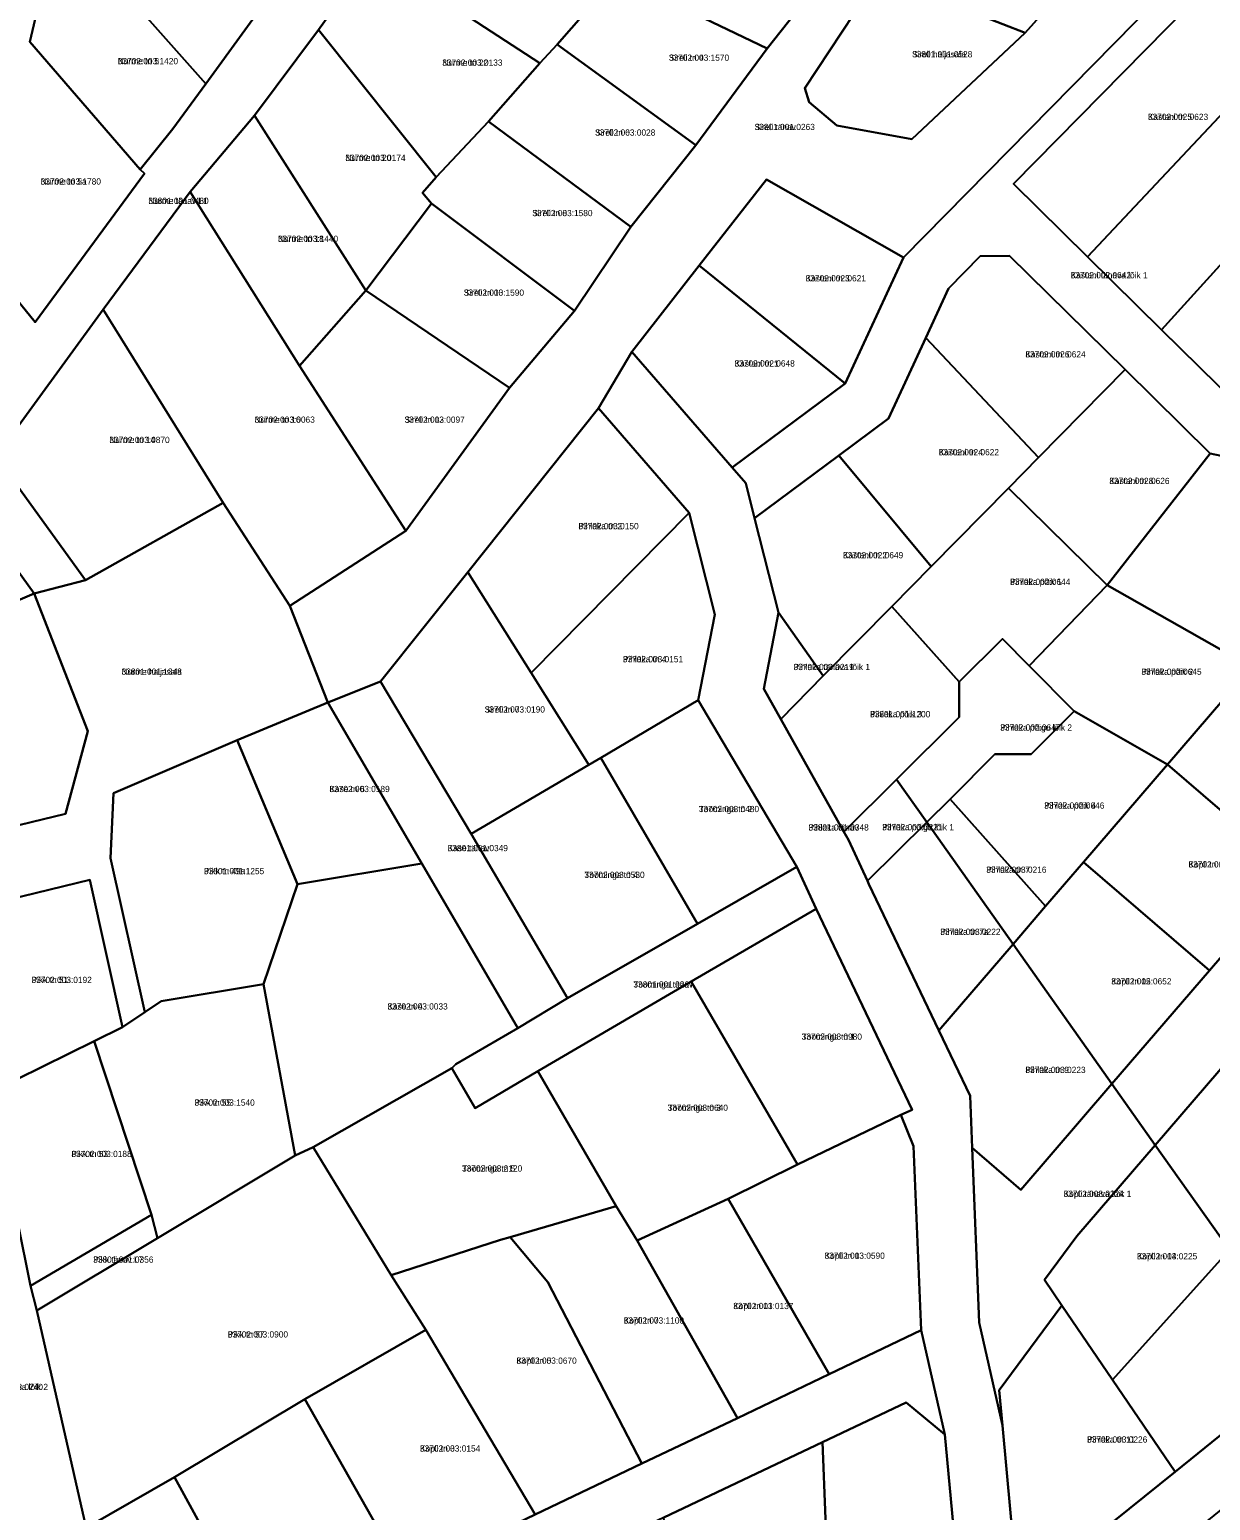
# Model space of a CAD drawing. Extents: x 551583 to 585220, y 6539942 to 6568852.
# Drawn here: x 566836.4 to 567120.7, y 6560564.2 to 6560920.6 of the extents above; entities that cross this region are included whole.
import ezdxf

# ---------------------------------------------------------------- set-up
doc = ezdxf.new("R2010")
doc.units = 0
for name, color, linetype in [('L_AADRESS', 7, 'Continuous'), ('PIIR', 7, 'Continuous'), ('TUNNUS', 7, 'Continuous')]:
    doc.layers.add(name, color=color, linetype=linetype)

msp = doc.modelspace()

# ---------------------------------------------------------------- linework, layer by layer
at = {"layer": 'PIIR'}
for points in [[(567103.65, 6560958.96), (567105.34, 6560952.59), (567076.12, 6560919.88), (567054.59, 6560928.31), (567066.71, 6560957.02), (567070.6, 6560967.27), (567072.05, 6560971.64)], [(566824.24, 6560964.21), (566848.08, 6560967.35), (566843.44, 6560947.46), (566836.5, 6560917.68), (566863.07, 6560886.94), (566864.07, 6560886.01), (566837.76, 6560850.18), (566827.3, 6560862.99), (566826.14, 6560904.44), (566821.12, 6560930.5), (566814.13, 6560962.93)], [(566906.38, 6560945.57), (566878.83, 6560907.59), (566843.44, 6560947.46), (566848.08, 6560967.35), (566866.74, 6560969.67), (566894.71, 6560952.95)], [(566931.8, 6560955.94), (566977.76, 6560933.49), (566963.43, 6560917.09), (566959.26, 6560912.6), (566919.09, 6560938.77)], [(566977.76, 6560933.49), (566988.09, 6560955.16), (567007.18, 6560946.96), (567030.82, 6560937.46), (567013.96, 6560916.09)], [(566878.83, 6560907.59), (566870.93, 6560896.74), (566863.07, 6560886.94), (566836.5, 6560917.68), (566843.44, 6560947.46)], [(566919.09, 6560938.77), (566959.26, 6560912.6), (566946.87, 6560898.56), (566934.32, 6560885.13), (566905.97, 6560920.56)], [(567073.26, 6560883.48), (567126.11, 6560937.17), (567138.02, 6560915.86), (567091.08, 6560865.94)], [(566963.43, 6560917.09), (566977.76, 6560933.49), (567013.96, 6560916.09), (566996.82, 6560892.79)], [(567023.08, 6560906.52), (567040.84, 6560933.6), (567054.59, 6560928.31), (567076.12, 6560919.88), (567048.78, 6560894.31), (567030.72, 6560897.59), (567024.08, 6560903.14)], [(566890.53, 6560899.97), (566905.97, 6560920.56), (566934.32, 6560885.13), (566931.02, 6560881.32), (566933.19, 6560878.76), (566917.34, 6560857.85)], [(566996.82, 6560892.79), (566981.15, 6560873.16), (566946.87, 6560898.56), (566959.26, 6560912.6), (566963.43, 6560917.09)], [(567091.08, 6560865.94), (567138.02, 6560915.86), (567150.25, 6560893.97), (567108.9, 6560848.4)], [(566890.53, 6560899.97), (566917.34, 6560857.85), (566901.42, 6560839.74), (566875.06, 6560881.6)], [(566931.02, 6560881.32), (566934.32, 6560885.13), (566946.87, 6560898.56), (566981.15, 6560873.16), (566967.56, 6560852.91), (566933.19, 6560878.76)], [(567108.9, 6560848.4), (567150.25, 6560893.97), (567151.94, 6560890.96), (567168.99, 6560898.46), (567175.99, 6560888.5), (567127.03, 6560830.55)], [(566875.06, 6560881.6), (566901.42, 6560839.74), (566927.02, 6560799.96), (566899.11, 6560781.95), (566882.99, 6560806.76), (566854.16, 6560853.3)], [(566997.64, 6560863.86), (567013.84, 6560884.59), (567046.8, 6560865.82), (567032.77, 6560835.46)], [(566933.19, 6560878.76), (566967.56, 6560852.91), (566951.94, 6560834.4), (566917.34, 6560857.85)], [(566981.44, 6560843.11), (566997.64, 6560863.86), (567032.77, 6560835.46), (567005.55, 6560815.21)], [(567052.14, 6560846.42), (567057.64, 6560858.34), (567065.27, 6560866.09), (567072.34, 6560866.15), (567100.13, 6560838.79), (567079.33, 6560817.66)], [(566901.42, 6560839.74), (566917.34, 6560857.85), (566951.94, 6560834.4), (566927.02, 6560799.96)], [(566854.16, 6560853.3), (566882.99, 6560806.76), (566849.86, 6560788.08), (566828.29, 6560817.87)], [(567031.24, 6560818.12), (567043.19, 6560827.01), (567052.14, 6560846.42), (567079.33, 6560817.66), (567072.07, 6560810.28), (567053.49, 6560791.4)], [(567072.07, 6560810.28), (567079.33, 6560817.66), (567100.13, 6560838.79), (567120.61, 6560818.64), (567095.83, 6560786.9)], [(566941.89, 6560790.02), (566973.41, 6560829.49), (566995.18, 6560804.31), (566957.13, 6560765.81)], [(567010.96, 6560803.02), (567031.24, 6560818.12), (567053.49, 6560791.4), (567044.03, 6560781.77), (567027.5, 6560765.04), (567016.71, 6560780.33)], [(567095.83, 6560786.9), (567120.61, 6560818.64), (567150.12, 6560812.31), (567123.42, 6560771.28)], [(567096.98, 6560666.86), (567120.45, 6560694.15), (567140.67, 6560717.66), (567160.88, 6560741.16), (567165.44, 6560746.47), (567192.97, 6560778.47), (567201.51, 6560788.4), (567226.17, 6560817.09), (567236.58, 6560802.28), (567212.89, 6560774.8), (567204.12, 6560764.6), (567174, 6560729.58), (567154.06, 6560706.39), (567132.1, 6560680.86), (567107.4, 6560652.13)], [(566783.62, 6560793.33), (566817.83, 6560812.12), (566837.54, 6560784.9), (566793.43, 6560766.04)], [(567044.03, 6560781.77), (567053.49, 6560791.4), (567072.07, 6560810.28), (567095.83, 6560786.9), (567077.03, 6560767.52), (567070.64, 6560773.95), (567060.23, 6560763.63)], [(566849.86, 6560788.08), (566882.99, 6560806.76), (566899.11, 6560781.95), (566908.2, 6560758.66), (566886.39, 6560749.58), (566856.6, 6560736.84), (566855.9, 6560721.21), (566864.13, 6560684.11), (566858.79, 6560680.48), (566850.93, 6560715.95), (566815.01, 6560707.21), (566808.94, 6560723.09), (566845.05, 6560731.87), (566850.45, 6560751.75), (566837.54, 6560784.9)], [(566957.13, 6560765.81), (566995.18, 6560804.31), (567001.35, 6560779.88), (566997.4, 6560759.23), (566973.93, 6560745.35), (566971.06, 6560743.67)], [(566920.91, 6560763.75), (566941.89, 6560790.02), (566957.13, 6560765.81), (566971.06, 6560743.67), (566942.76, 6560727.08)], [(567077.03, 6560767.52), (567095.83, 6560786.9), (567123.42, 6560771.28), (567130.55, 6560767.24), (567110.34, 6560743.74), (567087.91, 6560756.57)], [(566793.43, 6560766.04), (566837.54, 6560784.9), (566850.45, 6560751.75), (566845.05, 6560731.87), (566808.94, 6560723.09)], [(567027.5, 6560765.04), (567044.03, 6560781.77), (567060.23, 6560763.63), (567060.2, 6560755.12), (567045.14, 6560740.1), (567032.46, 6560727.52), (567017.28, 6560754.61)], [(567013.19, 6560761.95), (567016.71, 6560780.33), (567027.5, 6560765.04), (567017.28, 6560754.61)], [(567045.14, 6560740.1), (567060.2, 6560755.12), (567060.23, 6560763.63), (567070.64, 6560773.95), (567077.03, 6560767.52), (567087.91, 6560756.57), (567077.52, 6560746.24), (567068.79, 6560746.26), (567058.07, 6560735.41), (567052.43, 6560729.83)], [(566930.82, 6560719.87), (566908.2, 6560758.66), (566920.91, 6560763.75), (566942.74, 6560727.05), (566965.93, 6560687.48), (566953.93, 6560680.23)], [(567110.34, 6560743.74), (567130.55, 6560767.24), (567144.77, 6560755.02), (567155.57, 6560745.72), (567160.88, 6560741.16), (567140.67, 6560717.66)], [(566886.39, 6560749.58), (566908.2, 6560758.66), (566930.82, 6560719.87), (566900.9, 6560714.94)], [(566997.4, 6560759.23), (567021.13, 6560719.07), (566997.23, 6560705.36), (566973.93, 6560745.35)], [(567058.07, 6560735.41), (567068.79, 6560746.26), (567077.52, 6560746.24), (567087.91, 6560756.57), (567110.34, 6560743.74), (567090.13, 6560720.23), (567081.01, 6560709.63)], [(566855.9, 6560721.21), (566856.6, 6560736.84), (566886.39, 6560749.58), (566900.9, 6560714.94), (566892.74, 6560690.87), (566868.08, 6560686.79), (566864.13, 6560684.11)], [(566973.93, 6560745.35), (566997.23, 6560705.36), (566965.93, 6560687.48), (566942.74, 6560727.05), (566971.06, 6560743.67)], [(567090.13, 6560720.23), (567110.34, 6560743.74), (567140.67, 6560717.66), (567120.45, 6560694.15)], [(567032.46, 6560727.52), (567045.14, 6560740.1), (567052.43, 6560729.83), (567038.13, 6560715.69), (567033.56, 6560725.6)], [(567052.43, 6560729.83), (567058.07, 6560735.41), (567081.01, 6560709.63), (567073.17, 6560700.52)], [(567038.13, 6560715.69), (567052.43, 6560729.83), (567073.17, 6560700.52), (567055.3, 6560679.73), (567038.48, 6560714.92)], [(566930.82, 6560719.87), (566953.93, 6560680.23), (566939.06, 6560671.6), (566938.1, 6560670.66), (566904.65, 6560651.59), (566900.32, 6560649.63), (566892.74, 6560690.87), (566900.9, 6560714.94)], [(566997.23, 6560705.36), (567021.13, 6560719.07), (567025.75, 6560709), (566995.68, 6560691.51), (566958.8, 6560669.89), (566943.71, 6560661), (566938.1, 6560670.66), (566939.06, 6560671.6), (566953.93, 6560680.23), (566965.93, 6560687.48)], [(567073.17, 6560700.52), (567081.01, 6560709.63), (567090.13, 6560720.23), (567120.45, 6560694.15), (567096.98, 6560666.86)], [(566821.78, 6560686.63), (566815.01, 6560707.21), (566850.93, 6560715.95), (566858.79, 6560680.48), (566851.93, 6560677.14), (566827.21, 6560664.95)], [(567025.75, 6560709), (567048.92, 6560660.62), (567046.19, 6560659.36), (567021.26, 6560647.45), (566995.68, 6560691.51)], [(567055.3, 6560679.73), (567073.17, 6560700.52), (567096.98, 6560666.86), (567075.06, 6560641.37), (567063.32, 6560651.47), (567062.82, 6560664)], [(566900.32, 6560649.63), (566867.2, 6560629.72), (566865.77, 6560635.3), (566851.93, 6560677.14), (566858.79, 6560680.48), (566864.13, 6560684.11), (566868.08, 6560686.79), (566892.74, 6560690.87)], [(567021.26, 6560647.45), (567004.57, 6560639.21), (566982.7, 6560629.15), (566977.66, 6560637.4), (566958.8, 6560669.89), (566995.68, 6560691.51)], [(567107.4, 6560652.13), (567132.1, 6560680.86), (567153.34, 6560652.22), (567152.14, 6560651.14), (567125.27, 6560626.87)], [(566827.21, 6560664.95), (566851.93, 6560677.14), (566865.77, 6560635.3), (566836.68, 6560618.26)], [(566938.1, 6560670.66), (566943.71, 6560661), (566958.8, 6560669.89), (566977.66, 6560637.4), (566952.12, 6560629.97), (566949.78, 6560629.28), (566923.43, 6560620.82), (566904.65, 6560651.59)], [(567063.32, 6560651.47), (567075.06, 6560641.37), (567096.98, 6560666.86), (567107.4, 6560652.13), (567088.5, 6560630.15), (567080.74, 6560619.66), (567084.91, 6560613.53), (567069.82, 6560593.12), (567070.64, 6560584.64), (567065, 6560609.39)], [(567004.57, 6560639.21), (567021.26, 6560647.45), (567046.19, 6560659.36), (567049.17, 6560651.87), (567051.03, 6560607.53), (567028.91, 6560596.97)], [(566931.85, 6560607.62), (566902.72, 6560590.91), (566871.29, 6560572.14), (566850.05, 6560559.98), (566838.14, 6560612.31), (566867.2, 6560629.72), (566900.32, 6560649.63), (566904.65, 6560651.59), (566923.43, 6560620.82)], [(567080.74, 6560619.66), (567088.5, 6560630.15), (567107.4, 6560652.13), (567125.27, 6560626.87), (567097.1, 6560595.63), (567084.91, 6560613.53)], [(566982.7, 6560629.15), (567004.57, 6560639.21), (567028.91, 6560596.97), (567006.83, 6560586.38)], [(566977.66, 6560637.4), (566982.7, 6560629.15), (567006.83, 6560586.38), (566983.83, 6560575.45), (566961.19, 6560619.15), (566952.12, 6560629.97)], [(566838.14, 6560612.31), (566836.68, 6560618.26), (566865.77, 6560635.3), (566867.2, 6560629.72)], [(566952.12, 6560629.97), (566961.19, 6560619.15), (566983.83, 6560575.45), (566958.1, 6560563.21), (566931.85, 6560607.62), (566923.43, 6560620.82), (566949.78, 6560629.28)], [(567097.1, 6560595.63), (567125.27, 6560626.87), (567144.54, 6560599.63), (567112.16, 6560573.48)], [(567069.82, 6560593.12), (567084.91, 6560613.53), (567097.1, 6560595.63), (567112.16, 6560573.48), (567082.27, 6560549.35), (567073.54, 6560553.04), (567070.64, 6560584.64)], [(567028.91, 6560596.97), (567051.03, 6560607.53), (567056.75, 6560582.45), (567047.43, 6560590.12), (567027.27, 6560580.57), (566989.11, 6560562.49), (566964.33, 6560550.77), (566934.31, 6560536.2), (566910.78, 6560524.84), (566866.88, 6560503.62), (566859.61, 6560501.1), (566856.47, 6560520.08), (566862.9, 6560517.22), (566893.23, 6560532.1), (566926.88, 6560548.18), (566958.1, 6560563.21), (566983.83, 6560575.45), (567006.83, 6560586.38)], [(566902.72, 6560590.91), (566931.85, 6560607.62), (566958.09, 6560563.21), (566926.88, 6560548.18)], [(566902.72, 6560590.91), (566926.88, 6560548.18), (566893.23, 6560532.1), (566871.29, 6560572.14)], [(567027.27, 6560580.57), (567047.43, 6560590.12), (567056.75, 6560582.45), (567061.39, 6560532.53), (567030.2, 6560506.78)], [(566996.64, 6560480.67), (566989.11, 6560562.49), (567027.27, 6560580.57), (567030.2, 6560506.78), (567001.86, 6560484.1)], [(566871.29, 6560572.14), (566893.23, 6560532.1), (566862.9, 6560517.22), (566856.47, 6560520.08), (566850.05, 6560559.98)]]:
    msp.add_lwpolyline(points, close=True, dxfattribs=at)
for points in [[(567040.84, 6560933.6), (567023.08, 6560906.52), (567024.08, 6560903.14), (567030.72, 6560897.59), (567048.78, 6560894.31), (567076.12, 6560919.88), (567105.34, 6560952.59)], [(566919.09, 6560938.77), (566905.97, 6560920.56), (566890.53, 6560899.97), (566875.06, 6560881.6), (566854.16, 6560853.3), (566828.29, 6560817.87), (566849.86, 6560788.08), (566837.54, 6560784.9), (566817.83, 6560812.12), (566783.62, 6560793.33), (566776.49, 6560813.21), (566811.96, 6560832.98), (566819.26, 6560848.54), (566816.35, 6560860.93), (566827.3, 6560862.99), (566837.76, 6560850.18), (566864.07, 6560886.01), (566863.07, 6560886.94), (566870.93, 6560896.74), (566878.83, 6560907.59), (566906.38, 6560945.57)], [(567122.81, 6560943.08), (567046.8, 6560865.82), (567013.84, 6560884.59), (566997.64, 6560863.86), (566981.44, 6560843.11), (566973.41, 6560829.49), (566941.89, 6560790.02), (566920.91, 6560763.75), (566908.2, 6560758.66), (566899.11, 6560781.95), (566927.02, 6560799.96), (566951.94, 6560834.4), (566967.56, 6560852.91), (566981.15, 6560873.16), (566996.82, 6560892.79), (567013.96, 6560916.09), (567030.82, 6560937.46)], [(567150.12, 6560812.31), (567120.61, 6560818.64), (567100.13, 6560838.79), (567072.34, 6560866.15), (567065.27, 6560866.09), (567057.64, 6560858.34), (567052.14, 6560846.42), (567043.19, 6560827.01), (567031.24, 6560818.12), (567010.96, 6560803.02), (567008.85, 6560811.43), (567005.55, 6560815.21), (567032.77, 6560835.46), (567046.8, 6560865.82), (567122.81, 6560943.08)], [(567126.11, 6560937.17), (567073.26, 6560883.48), (567091.08, 6560865.94), (567108.9, 6560848.4), (567127.03, 6560830.55)], [(566757.01, 6560924.74), (566760.03, 6560900.2), (566767.17, 6560850.6), (566776.49, 6560813.21), (566783.62, 6560793.33), (566793.43, 6560766.04), (566808.94, 6560723.09), (566815.01, 6560707.21), (566821.78, 6560686.63), (566827.21, 6560664.95), (566836.68, 6560618.26), (566838.14, 6560612.31), (566850.05, 6560559.98), (566856.47, 6560520.08), (566859.61, 6560501.1), (566869.74, 6560439.78), (566877.73, 6560391.39), (566878.7, 6560385.53), (566885.64, 6560343.52), (566889.57, 6560319.24), (566894.87, 6560296.33), (566900.51, 6560273.1)], [(567061.39, 6560532.53), (567056.75, 6560582.45), (567051.03, 6560607.53), (567049.17, 6560651.87), (567046.19, 6560659.36), (567048.92, 6560660.62), (567025.75, 6560709), (567021.13, 6560719.07), (566997.4, 6560759.23), (567001.35, 6560779.88), (566995.18, 6560804.31), (566973.41, 6560829.49), (566981.44, 6560843.11), (567005.55, 6560815.21), (567008.85, 6560811.43), (567010.96, 6560803.02), (567016.71, 6560780.33), (567013.19, 6560761.95), (567017.28, 6560754.61), (567032.46, 6560727.52), (567033.56, 6560725.6), (567038.13, 6560715.69), (567038.48, 6560714.92), (567055.3, 6560679.73), (567062.82, 6560664), (567063.32, 6560651.47), (567065, 6560609.39), (567070.64, 6560584.64), (567073.54, 6560553.04)], [(567082.27, 6560549.35), (567112.16, 6560573.48), (567144.54, 6560599.63), (567152.65, 6560588.18), (567143.12, 6560580.44), (567119.8, 6560561.56)]]:
    msp.add_lwpolyline(points, dxfattribs=at)

# ---------------------------------------------------------------- texts
at = {"layer": 'L_AADRESS'}
for s, p in [('Nurme tn 5', (566857.66, 6560912.31)), ('Nurme tn 22', (566935.77, 6560911.95)), ('Sireli tn 4', (566990.32, 6560913.14)), ('Sireli haljasala', (567048.87, 6560913.96)), ('Kastani tn 5', (567105.64, 6560898.9)), ('Sireli tn 6', (566972.56, 6560895.12)), ('Sireli tänav', (567010.96, 6560896.46)), ('Nurme tn 20', (566912.43, 6560889.03)), ('Nurme tn 5a', (566839.1, 6560883.34)), ('Nurme tänav L1', (566865.02, 6560878.68)), ('Sireli tn 8', (566957.44, 6560875.74)), ('Nurme tn 18', (566896.2, 6560869.55)), ('Kastani tn 3', (567023.25, 6560860.03)), ('Kastani tänava lõik 1', (567087.06, 6560860.77)), ('Sireli tn 10', (566940.95, 6560856.58)), ('Kastani tn 6', (567076.14, 6560841.73)), ('Kastani tn 1', (567006.13, 6560839.54)), ('Nurme tn 16', (566890.59, 6560826)), ('Sireli tn 12', (566926.68, 6560826)), ('Nurme tn 14', (566855.64, 6560821.12)), ('Kastani tn 4', (567055.29, 6560818.16)), ('Kastani tn 8', (567096.34, 6560811.25)), ('Pihlaka tn 2', (566968.54, 6560800.37)), ('Kastani tn 2', (567032.23, 6560793.38)), ('Pihlaka põik 1', (567072.45, 6560786.96)), ('Pihlaka tn 4', (566979.24, 6560768.34)), ('Pihlaka tänava lõik 1', (567020.34, 6560766.46)), ('Nurme haljasala', (566858.57, 6560765.34)), ('Pihlaka põik 2', (567104.06, 6560765.32)), ('Sireli tn 7', (566945.98, 6560756.24)), ('Pihlaka põik 3', (567038.75, 6560755.1)), ('Pihlaka põigu lõik 2', (567070.08, 6560751.89)), ('Kase tn 6', (566908.61, 6560737.09)), ('Toominga tn 2', (566997.53, 6560732.27)), ('Pihlaka põik 4', (567080.66, 6560733.1)), ('Pihlaka tänav', (567023.93, 6560727.84)), ('Pihlaka põigu lõik 1', (567041.66, 6560727.9)), ('Kase tänav', (566937.07, 6560722.87)), ('Pikk tn 49a', (566878.4, 6560717.33)), ('Toominga tn 4', (566969.98, 6560716.42)), ('Pihlaka tn 7', (567066.72, 6560717.66)), ('Kopli tn 17', (567115.4, 6560718.94)), ('Pihlaka tn 7a', (567055.65, 6560702.71)), ('Pikk tn 51', (566836.9, 6560691.13)), ('Toominga tänav', (566981.78, 6560690.04)), ('Kopli tn 15', (567096.81, 6560690.79)), ('Kase tn 4', (566922.58, 6560684.75)), ('Toominga tn 1', (567022.3, 6560677.47)), ('Pihlaka tn 9', (567076.14, 6560669.47)), ('Pikk tn 55', (566876.12, 6560661.6)), ('Toominga tn 3', (566990.03, 6560660.36)), ('Pikk tn 53', (566846.49, 6560649.23)), ('Toominga tn 5', (566940.52, 6560645.74)), ('Kopli tänava lõik 1', (567085.36, 6560639.63)), ('Pikk tänav L7', (566851.74, 6560623.8)), ('Kopli tn 13', (567027.8, 6560624.74)), ('Kopli tn 14', (567103.01, 6560624.6)), ('Kopli tn 11', (567005.8, 6560612.63)), ('Kopli tn 7', (566979.47, 6560609.14)), ('Pikk tn 57', (566884.14, 6560605.79)), ('Kopli tn 5', (566953.63, 6560599.47)), ('Pika tänava lõik 2', (566825.14, 6560593.14)), ('Pihlaka tn 11', (567090.99, 6560580.5)), ('Kopli tn 3', (566930.41, 6560578.33))]:
    msp.add_text(s, height=1.5, dxfattribs=at).set_placement(p)
at = {"layer": 'TUNNUS'}
for s, p in [('33702:003:1420', (566857.66, 6560912.31)), ('33702:003:0133', (566935.77, 6560911.95)), ('33702:003:1570', (566990.32, 6560913.14)), ('33801:001:0528', (567048.87, 6560913.96)), ('33702:002:0623', (567105.64, 6560898.9)), ('33702:003:0028', (566972.56, 6560895.12)), ('33801:001:0263', (567010.96, 6560896.46)), ('33702:003:0174', (566912.43, 6560889.03)), ('33702:003:1780', (566839.1, 6560883.34)), ('33801:001:0480', (566865.02, 6560878.68)), ('33702:003:1580', (566957.44, 6560875.74)), ('33702:003:1440', (566896.2, 6560869.55)), ('33702:002:0621', (567023.25, 6560860.03)), ('33702:002:0642', (567087.06, 6560860.77)), ('33702:003:1590', (566940.95, 6560856.58)), ('33702:002:0624', (567076.14, 6560841.73)), ('33702:002:0648', (567006.13, 6560839.54)), ('33702:003:0063', (566890.59, 6560826)), ('33702:003:0097', (566926.68, 6560826)), ('33702:003:0870', (566855.64, 6560821.12)), ('33702:002:0622', (567055.29, 6560818.16)), ('33702:002:0626', (567096.34, 6560811.25)), ('33702:003:0150', (566968.54, 6560800.37)), ('33702:002:0649', (567032.23, 6560793.38)), ('33702:002:0644', (567072.45, 6560786.96)), ('33702:003:0151', (566979.24, 6560768.34)), ('33702:003:0219', (567020.34, 6560766.46)), ('33801:001:1348', (566858.57, 6560765.34)), ('33702:002:0645', (567104.06, 6560765.32)), ('33702:003:0190', (566945.98, 6560756.24)), ('33801:001:1200', (567038.75, 6560755.1)), ('33702:002:0647', (567070.08, 6560751.89)), ('33702:003:0189', (566908.61, 6560737.09)), ('33702:003:0480', (566997.53, 6560732.27)), ('33702:002:0646', (567080.66, 6560733.1)), ('33801:001:0348', (567023.93, 6560727.84)), ('33702:003:0221', (567041.66, 6560727.9)), ('33801:001:0349', (566937.07, 6560722.87)), ('33801:001:1255', (566878.4, 6560717.33)), ('33702:003:0530', (566969.98, 6560716.42)), ('33702:003:0216', (567066.72, 6560717.66)), ('33702:002:0654', (567115.4, 6560718.94)), ('33702:003:0222', (567055.65, 6560702.71)), ('33702:003:0192', (566836.9, 6560691.13)), ('33801:001:0267', (566981.78, 6560690.04)), ('33702:002:0652', (567096.81, 6560690.79)), ('33702:003:0033', (566922.58, 6560684.75)), ('33702:003:0980', (567022.3, 6560677.47)), ('33702:003:0223', (567076.14, 6560669.47)), ('33702:003:1540', (566876.12, 6560661.6)), ('33702:003:0640', (566990.03, 6560660.36)), ('33702:003:0188', (566846.49, 6560649.23)), ('33702:003:2120', (566940.52, 6560645.74)), ('33702:003:0224', (567085.36, 6560639.63)), ('33801:001:0356', (566851.74, 6560623.8)), ('33702:003:0590', (567027.8, 6560624.74)), ('33702:003:0225', (567103.01, 6560624.6)), ('33702:003:0137', (567005.8, 6560612.63)), ('33702:003:1100', (566979.47, 6560609.14)), ('33702:003:0900', (566884.14, 6560605.79)), ('33702:003:0670', (566953.63, 6560599.47)), ('33702:003:0240', (566825.14, 6560593.14)), ('33702:003:0226', (567090.99, 6560580.5)), ('33702:003:0154', (566930.41, 6560578.33))]:
    msp.add_text(s, height=1.5, dxfattribs=at).set_placement(p)

doc.saveas('drawing.dxf')
